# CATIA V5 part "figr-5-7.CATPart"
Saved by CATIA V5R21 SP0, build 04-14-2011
Part number: Part1
Bounding box of the stored display mesh (mm): x 0 to 150, y -70 to 70, z -150 to 69.804
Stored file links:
  D:\CATIA V5R21 E-RESOURCES\CATIA-V5R21\catia-v5r21-prt\c05-catia-v5r20-prt\catia-v5r21-figr-5-7.CATPart
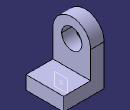
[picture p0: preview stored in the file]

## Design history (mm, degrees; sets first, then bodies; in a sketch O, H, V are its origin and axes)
Set1
  Plane1: type OffsetPt, RefPlane face of Pad2, RefPoint Sketch3
Body1 (main body)
  Sketch1 on yz-plane, origin (0, 0, 0), H (0, 1, 0), V (0, 0, 1)
    arc A1 centre (0, 0) radius 70 from (70, 0) to (-70, 0) ccw
    point P1 (70, 0)
    point P2 (-70, 0)
    line L1 (-70, 0) -> (-70, -150)
    line L2 (-70, -150) -> (70, -150)
    line L3 (70, -150) -> (70, 0)
    circle A2 centre (0, 0) radius 37.5
    radius A1 = 70
    radius A2 = 37.5
    distance O L2 = 150
    coincidence: P1 H, P2 H
    tangency: L1 A1, L3 A1
    horizontal: L2 H
  Pad1: profile Sketch1, direction (1, 0, 0), length 50
  Sketch2 on face of Pad1, origin (50, 0, 0), H (0, 1, 0), V (0, 0, 1)
    line L1 (-70, -150) -> (70, -150)
    line L2 (70, -150) -> (70, -100)
    line L3 (70, -100) -> (-70, -100)
    line L4 (-70, -100) -> (-70, -150)
    reference projected line E1 (-70, -150) -> (70, -150) from edge [face of Pad1 | face of Pad1]
    reference projected line E2 (-70, 0) -> (-70, -150) from edge [face of Pad1 | face of Pad1]
    reference projected line E3 (70, -150) -> (70, 0) from edge [face of Pad1 | face of Pad1]
    length L2 = 50
    horizontal: L1 H, L3 H
    vertical: L2 V, L4 V
    coincidence: L1 E1, E2 L4, L2 E3
  Pad2: profile Sketch2, direction (1, 0, 0), length 100
  Sketch3 on face of Pad2, origin (0, 0, -100), H (1, 0, 0), V (0, 1, 0)
    point P1 (110, 20)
